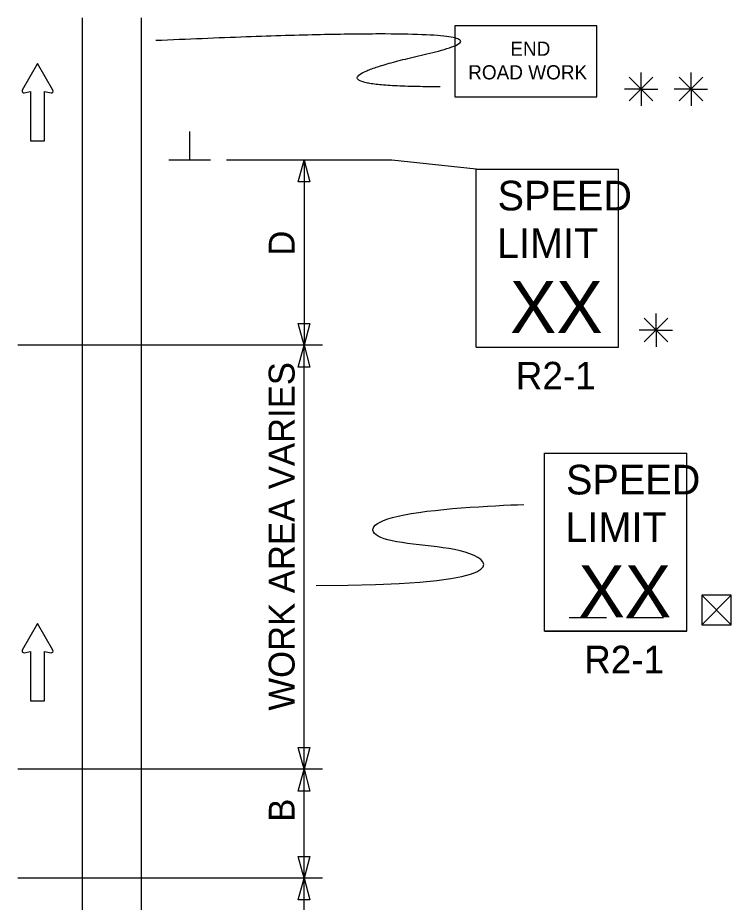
# Model space of a CAD drawing. Extents: x 16489 to 18480, y 5759 to 7026.
# Drawn here: x 16942.3 to 17135.1, y 6687.7 to 6926.7 of the extents above; entities that cross this region are included whole.
import ezdxf

# ---------------------------------------------------------------- set-up
doc = ezdxf.new("R2010")
doc.units = 0
for name, color, linetype in [('MT_SCRATCH_LEVEL_E', 7, 'Continuous'), ('PAVT_EDGE_EX', 7, 'Continuous'), ('TRAFFIC_SIGNS_PR', 7, 'Continuous'), ('TYPICAL_TEXT_DIMEN_PR', 7, 'Continuous')]:
    doc.layers.add(name, color=color, linetype=linetype)

msp = doc.modelspace()

# ---------------------------------------------------------------- linework, layer by layer
at = {"layer": 'MT_SCRATCH_LEVEL_E'}
for p, q in [((16947.62, 6914.3), (16943.51, 6907.06)), ((16951.77, 6907.06), (16947.62, 6914.3)), ((16943.99, 6906.37), (16945.77, 6906.69)), ((16945.77, 6906.69), (16945.77, 6893.43)), ((16949.51, 6893.43), (16949.51, 6906.69)), ((16949.51, 6906.69), (16951.29, 6906.37)), ((16945.77, 6893.43), (16949.51, 6893.43)), ((16947.62, 6763.02), (16943.51, 6755.78)), ((16951.77, 6755.78), (16947.62, 6763.02)), ((16943.99, 6755.1), (16945.77, 6755.41)), ((16945.77, 6755.41), (16945.77, 6742.15)), ((16949.51, 6742.15), (16949.51, 6755.41)), ((16949.51, 6755.41), (16951.29, 6755.1)), ((16945.77, 6742.15), (16949.51, 6742.15))]:
    msp.add_line(p, q, dxfattribs=at)
for centre, start, end in [((16943.92, 6906.83), 150.4248, 279.9638), ((16951.36, 6906.83), 260.0362, 29.7731), ((16943.92, 6755.56), 150.4248, 279.9638), ((16951.36, 6755.56), 260.0362, 29.7731)]:
    msp.add_arc(centre, 0.463, start, end, dxfattribs=at)
at = {"layer": 'PAVT_EDGE_EX'}
for p, q in [((16959.66, 6926.66), (16959.66, 6108.7)), ((16975.66, 6926.66), (16975.66, 6108.7))]:
    msp.add_line(p, q, dxfattribs=at)
at = {"layer": 'TRAFFIC_SIGNS_PR'}
for p, q in [((17066.18, 6885.75), (17104.63, 6885.75)), ((17066.18, 6837.69), (17066.18, 6885.75)), ((17104.63, 6837.69), (17104.63, 6885.75)), ((17066.18, 6837.69), (17104.63, 6837.69)), ((17084.68, 6809.02), (17123.08, 6809.02)), ((17084.68, 6761.02), (17084.68, 6809.02)), ((17084.68, 6809.02), (17123.13, 6809.02)), ((17084.68, 6760.96), (17084.68, 6809.02)), ((17123.08, 6761.02), (17123.08, 6809.02)), ((17123.13, 6760.96), (17123.13, 6809.02)), ((17091.33, 6764.67), (17101.38, 6764.67)), ((17106.76, 6764.67), (17116.82, 6764.67)), ((17084.68, 6761.02), (17123.08, 6761.02)), ((17084.68, 6760.96), (17123.13, 6760.96))]:
    msp.add_line(p, q, dxfattribs=at)
msp.add_lwpolyline([(17060.4, 6905.24), (17098.8, 6905.24), (17098.8, 6924.44), (17060.4, 6924.44)], close=True, dxfattribs=at)
msp.add_open_spline([(17056.4, 6908), (17013.89, 6908), (17090.41, 6925.41), (16979.62, 6920.47)], degree=2, dxfattribs=at)
at = {"layer": 'TYPICAL_TEXT_DIMEN_PR'}
for p, q in [((17110.74, 6907.37), (17110.74, 6911.82)), ((17124.24, 6907.37), (17124.24, 6911.82)), ((17107.55, 6910.56), (17113.93, 6904.18)), ((17113.93, 6910.56), (17107.55, 6904.18)), ((17121.06, 6910.56), (17127.43, 6904.18)), ((17127.43, 6910.56), (17121.06, 6904.18)), ((17110.74, 6907.37), (17106.21, 6907.37)), ((17110.74, 6907.37), (17113.93, 6907.37)), ((17110.74, 6907.37), (17115.22, 6907.37)), ((17110.74, 6907.37), (17110.74, 6902.87)), ((17124.24, 6907.37), (17119.71, 6907.37)), ((17124.24, 6907.37), (17127.43, 6907.37)), ((17124.24, 6907.37), (17128.72, 6907.37)), ((17124.24, 6907.37), (17124.24, 6902.87)), ((16988.79, 6888.16), (16988.79, 6895.95)), ((16994.41, 6888.16), (16983.16, 6888.16)), ((17043.4, 6888.16), (16998.66, 6888.16)), ((17018.09, 6882.3), (17019.66, 6888.16)), ((17019.66, 6888.16), (17019.66, 6838.16)), ((17019.66, 6888.16), (17021.23, 6882.3)), ((17066.18, 6885.75), (17043.4, 6888.16)), ((17019.66, 6882.3), (17018.09, 6882.3)), ((17021.23, 6882.3), (17019.66, 6882.3)), ((17114.79, 6842.26), (17114.79, 6846.71)), ((17019.66, 6838.16), (17018.09, 6844.02)), ((17018.09, 6844.02), (17019.66, 6844.02)), ((17019.66, 6844.02), (17021.23, 6844.02)), ((17021.23, 6844.02), (17019.66, 6838.16)), ((17111.6, 6845.45), (17117.97, 6839.07)), ((17117.97, 6845.45), (17111.6, 6839.07)), ((17114.79, 6842.26), (17110.26, 6842.26)), ((17114.79, 6842.26), (17117.97, 6842.26)), ((17114.79, 6842.26), (17119.26, 6842.26)), ((17114.79, 6842.26), (17114.79, 6837.76)), ((17024.66, 6838.16), (16942.27, 6838.16)), ((17018.09, 6832.3), (17019.66, 6838.16)), ((17019.66, 6723.62), (17019.66, 6838.16)), ((17019.66, 6838.16), (17021.23, 6832.3)), ((17019.66, 6832.3), (17018.09, 6832.3)), ((17021.23, 6832.3), (17019.66, 6832.3)), ((17127.12, 6770.69), (17135.12, 6762.69)), ((17127.12, 6762.69), (17135.12, 6770.69)), ((17019.66, 6723.62), (17018.09, 6729.49)), ((17018.09, 6729.49), (17019.66, 6729.49)), ((17019.66, 6729.49), (17021.23, 6729.49)), ((17021.23, 6729.49), (17019.66, 6723.62)), ((17024.66, 6723.62), (16942.27, 6723.62)), ((17018.09, 6717.76), (17019.66, 6723.62)), ((17019.66, 6694.2), (17019.66, 6723.62)), ((17019.66, 6723.62), (17021.23, 6717.76)), ((17019.66, 6717.76), (17018.09, 6717.76)), ((17021.23, 6717.76), (17019.66, 6717.76)), ((17019.66, 6694.2), (17018.09, 6700.06)), ((17018.09, 6700.06), (17019.66, 6700.06)), ((17019.66, 6700.06), (17021.23, 6700.06)), ((17021.23, 6700.06), (17019.66, 6694.2)), ((17024.66, 6694.2), (16942.27, 6694.2)), ((17018.09, 6688.34), (17019.66, 6694.2)), ((17019.66, 6663.63), (17019.66, 6694.2)), ((17019.66, 6694.2), (17021.23, 6688.34)), ((17019.66, 6688.34), (17018.09, 6688.34)), ((17021.23, 6688.34), (17019.66, 6688.34))]:
    msp.add_line(p, q, dxfattribs=at)
msp.add_lwpolyline([(17127.12, 6770.69), (17127.12, 6762.69), (17135.12, 6762.69), (17135.12, 6770.69)], close=True, dxfattribs=at)
msp.add_open_spline([(17022.97, 6773.31), (17071.44, 6773.31), (17071.44, 6784.07), (17036.52, 6784.07), (17036.52, 6793.11), (17070.73, 6794.88), (17079.02, 6795.17)], degree=3, dxfattribs=at)

# ---------------------------------------------------------------- texts
at = {"layer": 'TRAFFIC_SIGNS_PR'}
for s, height, p in [('END', 3.831, (17075.4, 6916.37)), ('ROAD WORK', 3.831, (17064.01, 6909.99)), ('SPEED', 8.01, (17071.96, 6874.6)), ('LIMIT', 8.01, (17071.8, 6861.78)), ('XX', 14.048, (17075.31, 6841.45)), ('R2-1', 7.449, (17076.87, 6826.24)), ('SPEED', 8, (17090.45, 6797.88)), ('SPEED', 8.01, (17090.45, 6797.87)), ('LIMIT', 8, (17090.28, 6785.08)), ('LIMIT', 8.01, (17090.29, 6785.05)), ('XX', 14.048, (17093.8, 6764.72)), ('R2-1', 7.44, (17095.36, 6749.58)), ('R2-1', 7.449, (17095.37, 6749.51))]:
    msp.add_text(s, height=height, dxfattribs=at).set_placement(p)
at = {"layer": 'TYPICAL_TEXT_DIMEN_PR'}
for s, p in [('D', (17017.1, 6862.38)), ('WORK AREA VARIES', (17017.1, 6739.48)), ('B', (17017.1, 6709.46))]:
    msp.add_text(s, height=7, rotation=90, dxfattribs=at).set_placement(p)

doc.saveas('drawing.dxf')
